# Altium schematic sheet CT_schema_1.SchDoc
size 397 x 258 mm
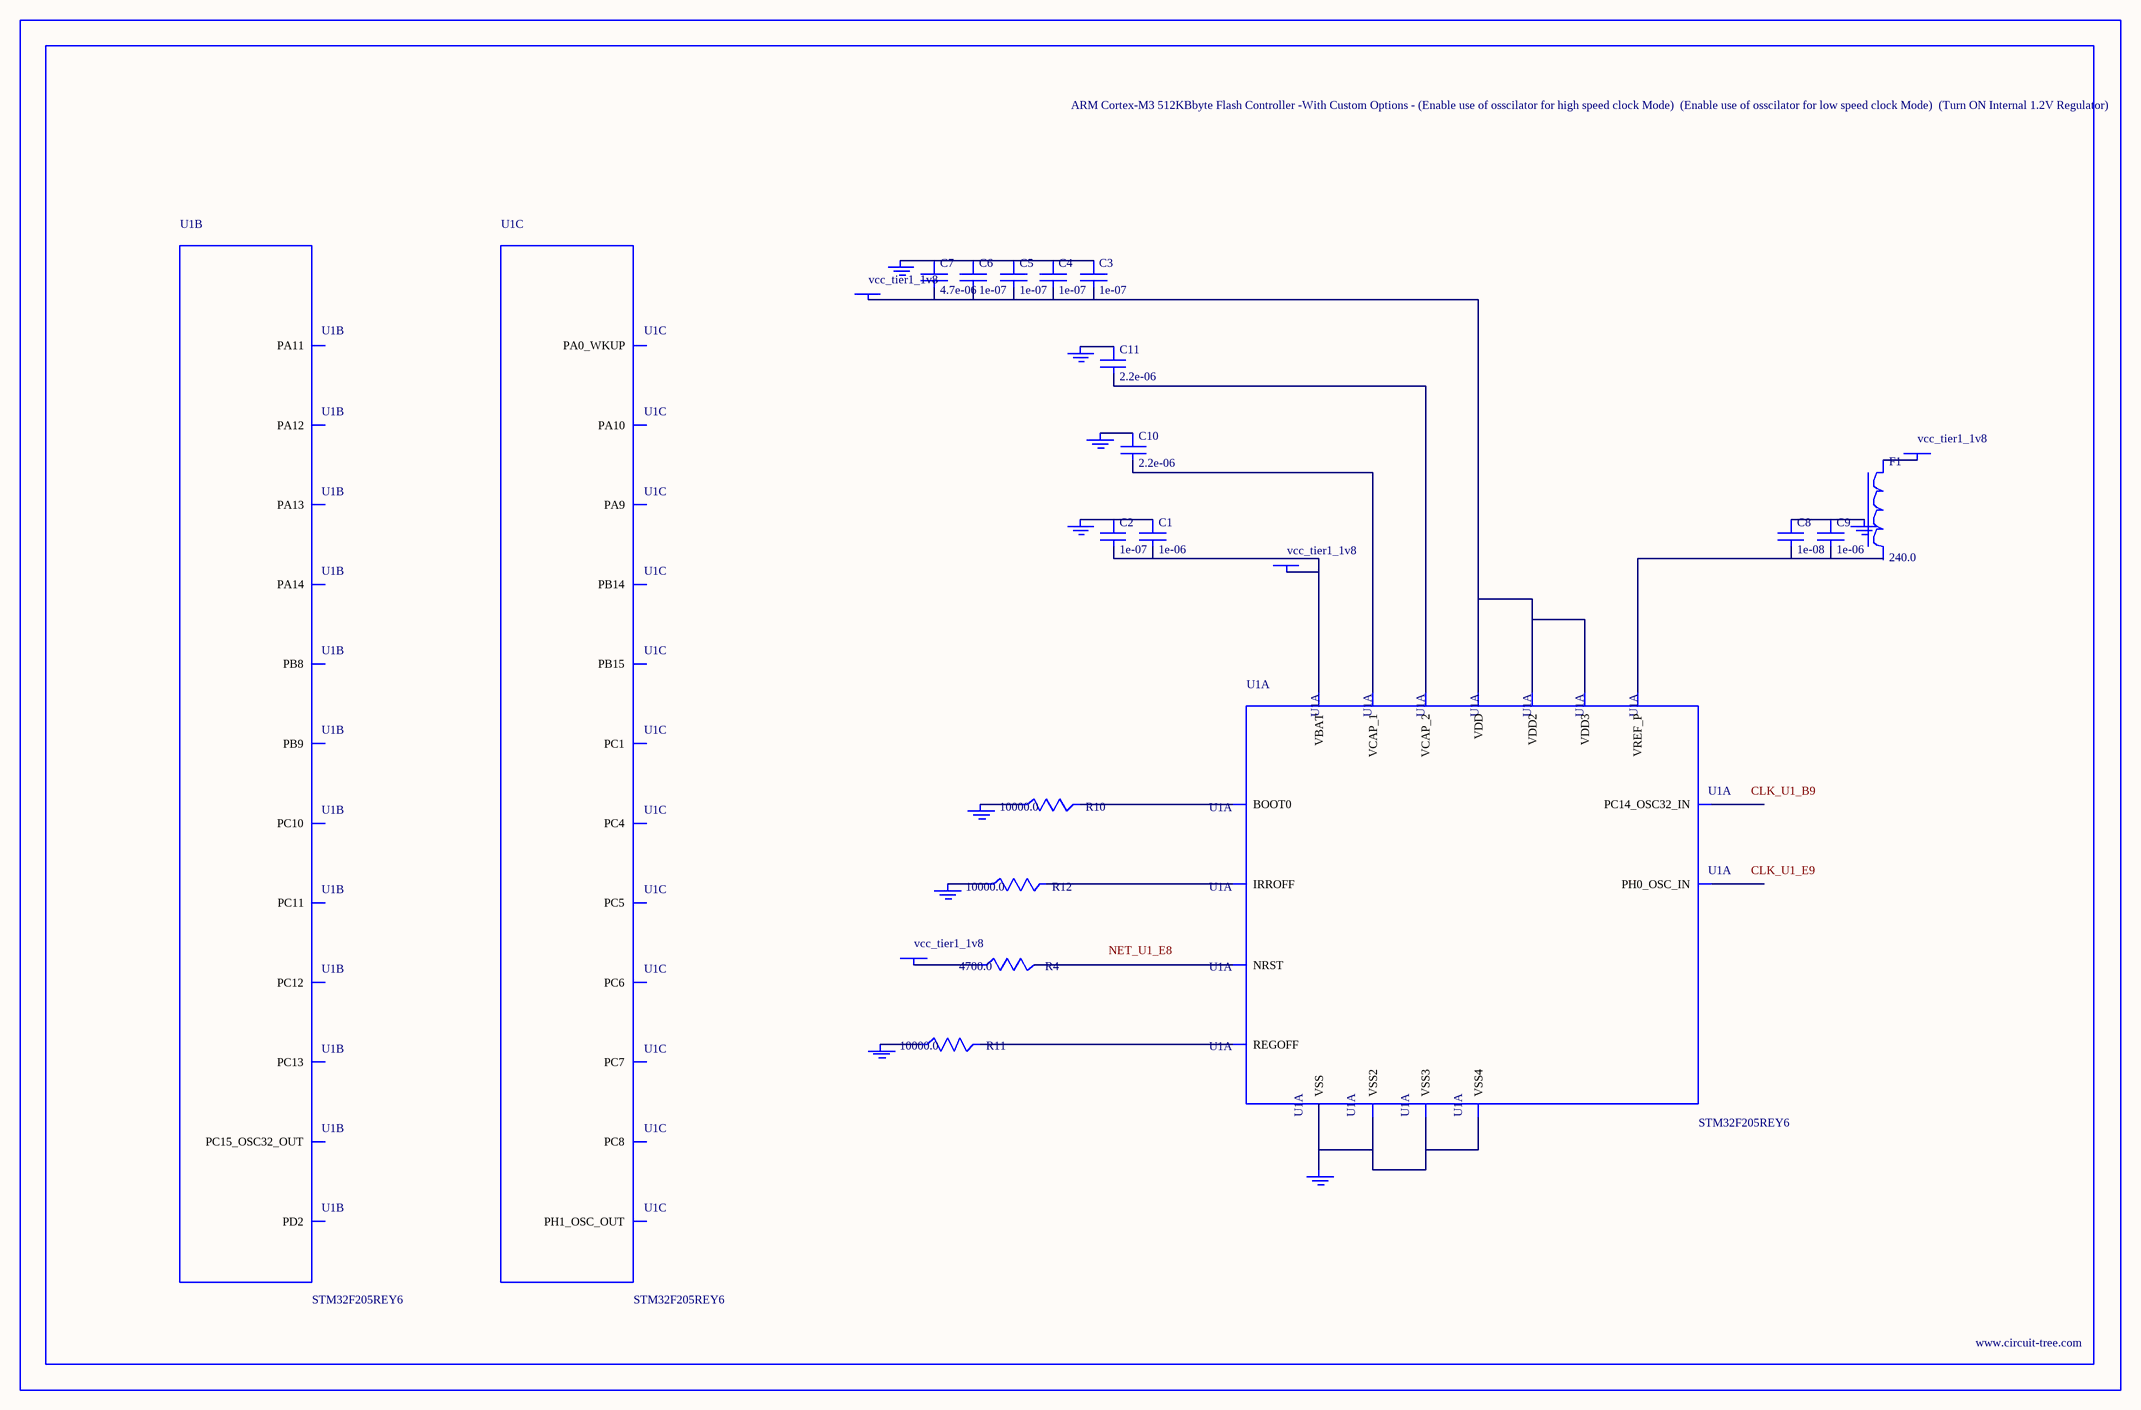
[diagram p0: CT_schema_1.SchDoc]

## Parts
BORDER0  (no value)
C1  1e-06  [C0603]
C2  1e-07  [C0603]
C3  1e-07  [C0603]
C4  1e-07  [C0603]
C5  1e-07  [C0603]
C6  1e-07  [C0603]
C7  4.7e-06  [C0603]
C8  1e-08  [C0603]
C9  1e-06  [C0603]
C10  2.2e-06  [C0603]
C11  2.2e-06  [C0603]
F1  240.0  [L0603]
GND_INSTANCE_0_0  (no value)
GND_INSTANCE_0_1  (no value)
GND_INSTANCE_0_2  (no value)
GND_INSTANCE_0_3  (no value)
GND_INSTANCE_0_4  (no value)
GND_INSTANCE_0_5  (no value)
GND_INSTANCE_0_6  (no value)
GND_INSTANCE_0_7  (no value)
GND_INSTANCE_0_8  (no value)
POWER_INSTANCE_0_0  vcc_tier1_1v8
POWER_INSTANCE_0_1  vcc_tier1_1v8
POWER_INSTANCE_0_2  vcc_tier1_1v8
POWER_INSTANCE_0_3  vcc_tier1_1v8
R4  4700.0  [R0603]
R10  10000.0  [R0603]
R11  10000.0  [R0603]
R12  10000.0  [R0603]
U1  STM32F205REY6  [WLCSP66]  (parts A,B,C of 7)

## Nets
NetC1_1: C1.1 C2.1 GND_INSTANCE_0_0.0(GND)
NetC1_2: C1.2 C2.2 POWER_INSTANCE_0_0.0(PWR) U1.A9(VBAT)
NetC3_1: C3.1 C4.1 C5.1 C6.1 C7.1 GND_INSTANCE_0_1.0(GND)
NetC3_2: C3.2 C4.2 C5.2 C6.2 C7.2 POWER_INSTANCE_0_1.0(PWR) U1.A8(VDD) U1.D9(VDD2) U1.E1(VDD3)
NetC8_1: C8.1 C9.1 GND_INSTANCE_0_3.0(GND)
NetC8_2: C8.2 C9.2 U1.F7(VREF_P)
NetC10_1: C10.1 GND_INSTANCE_0_6.0(GND)
NetC10_2: C10.2 U1.J3(VCAP_1)
NetC11_1: C11.1 GND_INSTANCE_0_7.0(GND)
NetC11_2: C11.2 U1.C2(VCAP_2)
NetF1_1: F1.1 POWER_INSTANCE_0_2.0(PWR)
NetGND_INSTANCE_0_2_0: GND_INSTANCE_0_2.0(GND) R10.1
NetGND_INSTANCE_0_4_0: GND_INSTANCE_0_4.0(GND) R11.1
NetGND_INSTANCE_0_5_0: GND_INSTANCE_0_5.0(GND) R12.1
NetGND_INSTANCE_0_8_0: GND_INSTANCE_0_8.0(GND) U1.B1(VSS) U1.D8(VSS2) U1.F1(VSS3) U1.H9(VSS4)
NetPOWER_INSTANCE_0_3_0: POWER_INSTANCE_0_3.0(PWR) R4.1
NetR4_2: R4.2 U1.E8(NRST)
NetR10_2: R10.2 U1.B6(BOOT0)
NetR11_2: R11.2 U1.H7(REGOFF)
NetR12_2: R12.2 U1.C8(IRROFF)

Not connected (* = marked no-connect by the designer): F1 2; U1 A1(PA14) A3(PC12) A7(PB9) B2(PA13) B3(PC10) B7(PB8) B8(PC13) B9(PC14_OSC32_IN) C1(PA12) C3(PC11) C7(PD2) C9(PC15_OSC32_OUT) D2(PA11) D3(PA10) E3(PA9) E7(PA0_WKUP) E9(PH0_OSC_IN) F2(PC7) F3(PC8) F8(PC1) F9(PH1_OSC_OUT) G1(PB15) G2(PC6) G3(PC5) H1(PB14) H4(PC4)

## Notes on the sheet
- Labels drawn without touching a wire or pin: CLK_U1_B9, CLK_U1_E9, NET_U1_E8

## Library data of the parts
BORDER0 = BORDER_PAGE0
C1 C9 = C0603C105K3RACTU
C2-C6 = 06035C104K4Z2A
C7 = GRM188R6YA475KE15D
C8 = 06035C103K4Z2A
C10 C11 = C0603C225K8RACTU
F1 = Z0603C241ASMST
GND_INSTANCE_0_0-GND_INSTANCE_0_8 = GND
POWER_INSTANCE_0_0-POWER_INSTANCE_0_3 = PWR
R4 = RC0603JR-074K7L
R10-R12 = RC0603JR-0710KL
